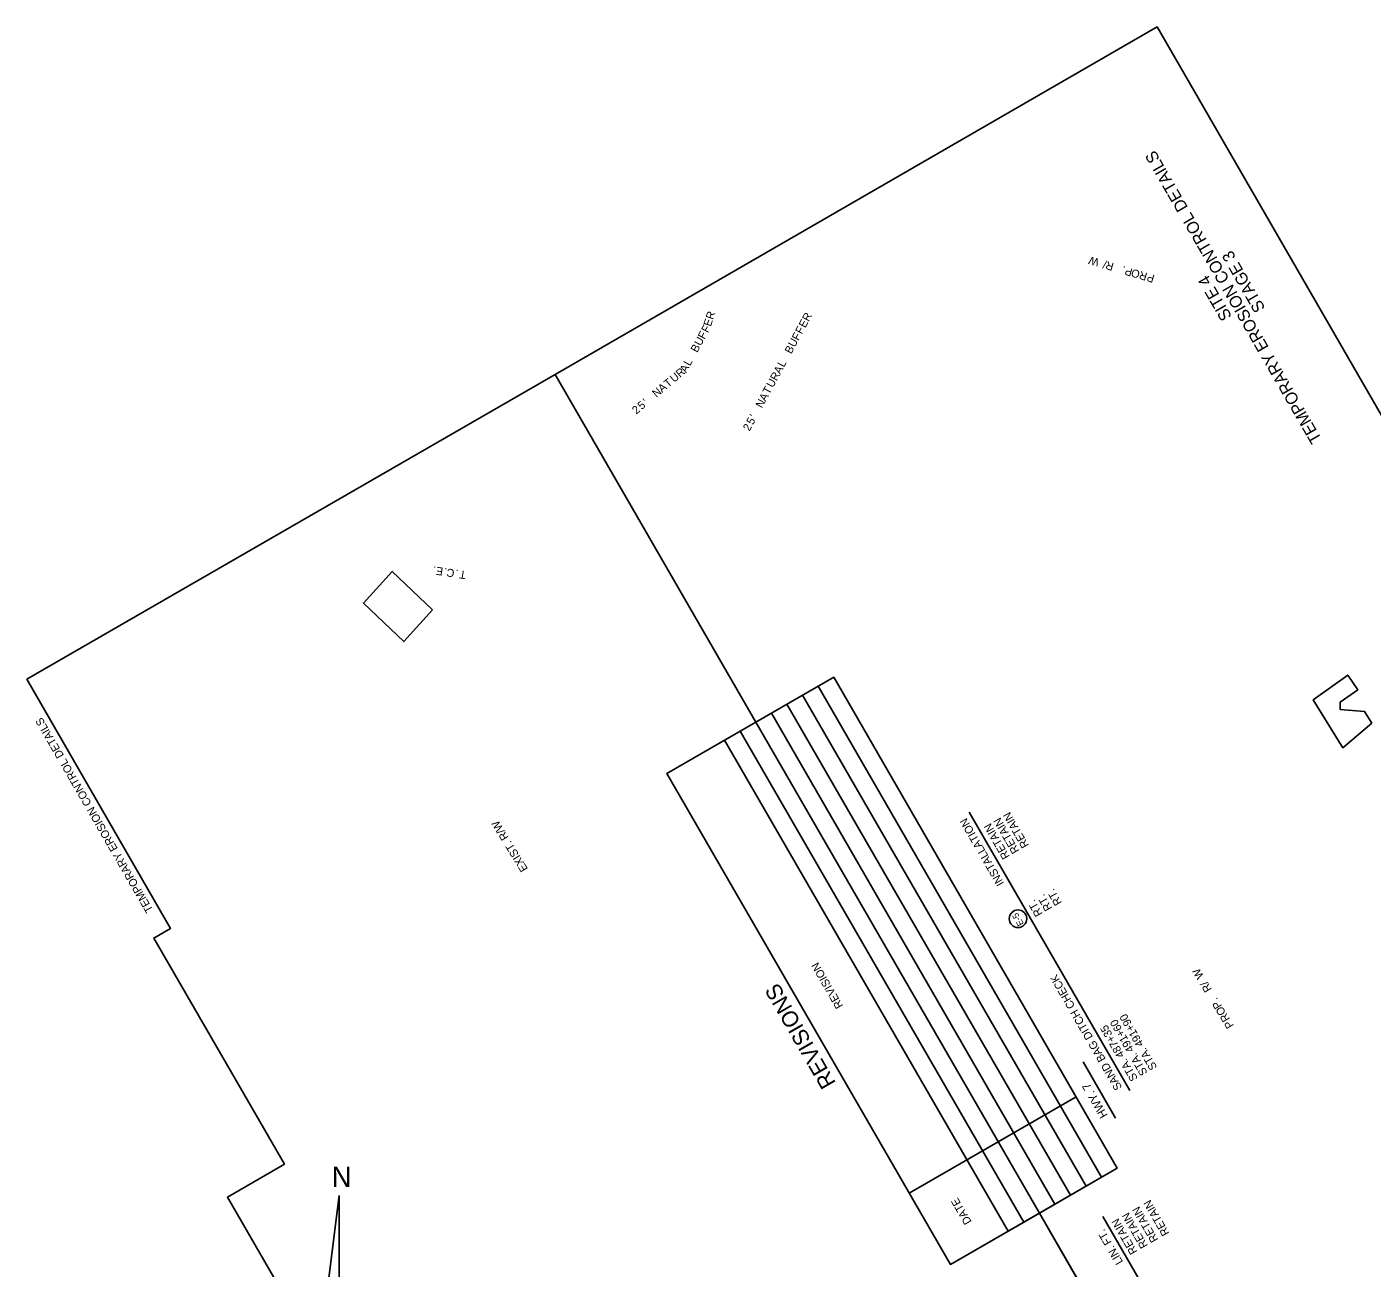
# Model space of a CAD drawing. Extents: x 956270 to 957915, y 1920520 to 1922423.
# Drawn here: x 956270 to 957279, y 1921493 to 1922423 of the extents above; entities that cross this region are included whole.
import ezdxf

# ---------------------------------------------------------------- set-up
doc = ezdxf.new("R2010")
doc.units = 0
for name, color, linetype in [('1', 7, 'Continuous'), ('44', 7, 'Continuous'), ('60', 7, 'Continuous'), ('63', 7, 'Continuous'), ('Default', 7, 'Continuous'), ('NO PLOT', 7, 'Continuous'), ('R_Draft', 7, 'Continuous')]:
    doc.layers.add(name, color=color, linetype=linetype)

msp = doc.modelspace()

# ---------------------------------------------------------------- linework, layer by layer
at = {"layer": '1'}
for p, q in [((956816.7, 1921902), (956666.2, 1922162.6)), ((957172.3, 1921286.1), (957029.2, 1921533.9))]:
    msp.add_line(p, q, dxfattribs=at)
msp.add_circle((957013.2, 1921754.6), 6.61, dxfattribs=at)
at = {"layer": '44'}
for p, q in [((957097.1, 1921625.8), (956976.5, 1921834.5)), ((957086.4, 1921605), (957062, 1921647.3)), ((957193.2, 1921329.7), (957076.8, 1921531.3))]:
    msp.add_line(p, q, dxfattribs=at)
at = {"layer": '63'}
for p, q in [((956504.3, 1921547), (956496.6, 1921485.5)), ((956504.3, 1921447), (956504.3, 1921547)), ((956504.3, 1921547), (956504.3, 1921470.1))]:
    msp.add_line(p, q, dxfattribs=at)
at = {"layer": 'Default'}
for p, q in [((956750, 1921863.5), (956875.1, 1921935.7)), ((957075.9, 1921560.9), (956863.4, 1921929)), ((957087.6, 1921567.7), (956875.1, 1921935.7)), ((957064.2, 1921554.2), (956851.7, 1921922.2)), ((957040.9, 1921540.7), (956828.4, 1921908.7)), ((957040.9, 1921540.7), (956828.4, 1921908.7)), ((957052.5, 1921547.4), (956840, 1921915.5)), ((957029.2, 1921533.9), (956816.7, 1921902)), ((957005.8, 1921520.4), (956793.3, 1921888.5)), ((957017.5, 1921527.2), (956805, 1921895.2)), ((956962.5, 1921495.4), (956750, 1921863.5)), ((956931.6, 1921548.9), (957056.7, 1921621.2)), ((956962.5, 1921495.4), (957087.6, 1921567.7))]:
    msp.add_line(p, q, dxfattribs=at)
at = {"layer": 'NO PLOT'}
for points in [[(957915.2, 1921041.6), (957117.5, 1922423.2), (956666.2, 1922162.6), (956816.7, 1921902), (956875.1, 1921935.7), (957087.6, 1921567.7), (957029.2, 1921533.9), (957172.3, 1921286.1), (957225.7, 1921317), (957397.1, 1921020.2), (957343.6, 1920989.3), (957463.8, 1920781)], [(957915.2, 1921041.6), (957117.5, 1922423.2), (956666.2, 1922162.6), (956816.7, 1921902), (956875.1, 1921935.7), (957087.6, 1921567.7), (957029.2, 1921533.9), (957172.3, 1921286.1), (957225.7, 1921317), (957397.1, 1921020.2), (957343.6, 1920989.3), (957463.8, 1920781)], [(957915.2, 1921041.6), (957117.5, 1922423.2), (956666.2, 1922162.6), (956816.7, 1921902), (956875.1, 1921935.7), (957087.6, 1921567.7), (957029.2, 1921533.9), (957172.3, 1921286.1), (957225.7, 1921317), (957397.1, 1921020.2), (957343.6, 1920989.3), (957463.8, 1920781)], [(957915.2, 1921041.6), (957117.5, 1922423.2), (956666.2, 1922162.6), (956816.7, 1921902), (956875.1, 1921935.7), (957087.6, 1921567.7), (957029.2, 1921533.9), (957172.3, 1921286.1), (957225.7, 1921317), (957397.1, 1921020.2), (957343.6, 1920989.3), (957463.8, 1920781)], [(957915.2, 1921041.6), (957117.5, 1922423.2), (956666.2, 1922162.6), (956816.7, 1921902), (956875.1, 1921935.7), (957087.6, 1921567.7), (957029.2, 1921533.9), (957172.3, 1921286.1), (957225.7, 1921317), (957397.1, 1921020.2), (957343.6, 1920989.3), (957463.8, 1920781)], [(957915.2, 1921041.6), (957117.5, 1922423.2), (956666.2, 1922162.6), (956816.7, 1921902), (956875.1, 1921935.7), (957087.6, 1921567.7), (957029.2, 1921533.9), (957172.3, 1921286.1), (957225.7, 1921317), (957397.1, 1921020.2), (957343.6, 1920989.3), (957463.8, 1920781)], [(957012.5, 1920520.4), (956420.5, 1921545.9), (956463.3, 1921570.6), (956365.4, 1921740.1), (956378, 1921747.4), (956270.3, 1921934.1), (956666.2, 1922162.6), (956816.7, 1921902), (956750, 1921863.5), (956962.5, 1921495.4), (957029.2, 1921533.9), (957172.3, 1921286.1), (957120.9, 1921256.4), (957292.2, 1920959.7), (957343.6, 1920989.3), (957463.8, 1920781)], [(957012.5, 1920520.4), (956420.5, 1921545.9), (956463.3, 1921570.6), (956365.4, 1921740.1), (956378, 1921747.4), (956270.3, 1921934.1), (956666.2, 1922162.6), (956816.7, 1921902), (956750, 1921863.5), (956962.5, 1921495.4), (957029.2, 1921533.9), (957172.3, 1921286.1), (957120.9, 1921256.4), (957292.2, 1920959.7), (957343.6, 1920989.3), (957463.8, 1920781)], [(957012.5, 1920520.4), (956420.5, 1921545.9), (956463.3, 1921570.6), (956365.4, 1921740.1), (956378, 1921747.4), (956270.3, 1921934.1), (956666.2, 1922162.6), (956816.7, 1921902), (956750, 1921863.5), (956962.5, 1921495.4), (957029.2, 1921533.9), (957172.3, 1921286.1), (957120.9, 1921256.4), (957292.2, 1920959.7), (957343.6, 1920989.3), (957463.8, 1920781)], [(957012.5, 1920520.4), (956420.5, 1921545.9), (956463.3, 1921570.6), (956365.4, 1921740.1), (956378, 1921747.4), (956270.3, 1921934.1), (956666.2, 1922162.6), (956816.7, 1921902), (956750, 1921863.5), (956962.5, 1921495.4), (957029.2, 1921533.9), (957172.3, 1921286.1), (957120.9, 1921256.4), (957292.2, 1920959.7), (957343.6, 1920989.3), (957463.8, 1920781)], [(957012.5, 1920520.4), (956420.5, 1921545.9), (956463.3, 1921570.6), (956365.4, 1921740.1), (956378, 1921747.4), (956270.3, 1921934.1), (956666.2, 1922162.6), (956816.7, 1921902), (956750, 1921863.5), (956962.5, 1921495.4), (957029.2, 1921533.9), (957172.3, 1921286.1), (957120.9, 1921256.4), (957292.2, 1920959.7), (957343.6, 1920989.3), (957463.8, 1920781)], [(957012.5, 1920520.4), (956420.5, 1921545.9), (956463.3, 1921570.6), (956365.4, 1921740.1), (956378, 1921747.4), (956270.3, 1921934.1), (956666.2, 1922162.6), (956816.7, 1921902), (956750, 1921863.5), (956962.5, 1921495.4), (957029.2, 1921533.9), (957172.3, 1921286.1), (957120.9, 1921256.4), (957292.2, 1920959.7), (957343.6, 1920989.3), (957463.8, 1920781)], [(956574.4, 1921986.1), (956552.8, 1921962.4), (956522.5, 1921991.3), (956544.1, 1922015)], [(957278.4, 1921901.1), (957273, 1921910), (957254.7, 1921911.4), (957254.7, 1921917), (957268, 1921926.3), (957260.4, 1921937.3), (957234.5, 1921918.7), (957256.8, 1921882.8)]]:
    msp.add_lwpolyline(points, close=True, dxfattribs=at)

# ---------------------------------------------------------------- texts
at = {"layer": '1'}
for s, height, p in [('TEMPORARY EROSION CONTROL DETAILS', 6, (956365.1, 1921761.2)), ('E-5 ', 4.8, (957017.7, 1921750.9))]:
    msp.add_text(s, height=height, rotation=120, dxfattribs=at).set_placement(p)
at = {"layer": '44'}
for s, height, p in [('INSTALLATION', 6, (957003, 1921781.2)), ('RETAIN', 6, (957014.4, 1921805.5)), ('RETAIN', 6, (957021.6, 1921809.7)), ('RETAIN', 6, (957007.2, 1921801.3)), ('RT.', 6, (957031.8, 1921758.3)), ('RT.', 6, (957039, 1921762.5)), ('RT.', 6, (957046.3, 1921766.6)), ('SAND BAG DITCH CHECK', 6, (957091.4, 1921628.1)), ('STA. 491+60', 6, (957110.5, 1921639.1)), ('STA. 491+90', 6, (957117.7, 1921643.2)), ('STA. 487+35', 6, (957103.2, 1921634.9)), ('HWY. 7', 6.25, (957080.7, 1921607.3)), ('RETAIN', 6, (957118.5, 1921514)), ('RETAIN', 6, (957126.9, 1921518.9)), ('RETAIN', 6, (957102.9, 1921505)), ('RETAIN', 6, (957110.7, 1921509.5)), ('LIN. FT.', 6, (957092.1, 1921497.3))]:
    msp.add_text(s, height=height, rotation=120, dxfattribs=at).set_placement(p)
at = {"layer": '60'}
for s, p in [('TEMPORARY EROSION CONTROL DETAILS', (957241.2, 1922114.1)), ('STAGE 3', (957198.8, 1922212.3)), ('SITE 4', (957173.8, 1922206.1))]:
    msp.add_text(s, height=9, rotation=120, dxfattribs=at).set_placement(p)
at = {"layer": '63'}
msp.add_text('N', height=15.4, rotation=360, dxfattribs=at).set_placement((956498.7, 1921553.4))
at = {"layer": 'Default'}
for s, height, p in [('REVISION', 6, (956882.3, 1921689.3)), ('REVISIONS', 12, (956877, 1921631.5)), ('DATE', 6, (956978.6, 1921527.4))]:
    msp.add_text(s, height=height, rotation=120, dxfattribs=at).set_placement(p)
at = {"layer": 'R_Draft'}
for s, rotation, p in [('W', 163.5297, (957074.5, 1922249.2)), ('/', 163.5297, (957080.1, 1922247.6)), ('R', 163.5297, (957085.5, 1922246)), ('.', 163.5297, (957094.1, 1922243.4)), ('P', 163.5297, (957099.5, 1922241.8)), ('O', 163.5297, (957105.1, 1922240.2)), ('R', 163.5297, (957110.6, 1922238.6)), ('P', 163.5297, (957116, 1922237)), ('E', 71.8782, (956782.9, 1922198.2)), ('R', 71.8782, (956784.6, 1922203.4)), ('E', 61.6353, (956853.7, 1922197.1)), ('R', 61.6353, (956856.3, 1922201.9)), ('U', 61.6353, (956775.4, 1922183.6)), ('F', 61.6353, (956778.1, 1922188.6)), ('F', 61.6353, (956780.7, 1922193.4)), ('F', 61.6353, (956848.6, 1922187.6)), ('F', 61.6353, (956851.1, 1922192.4)), ('B', 61.6353, (956772.7, 1922178.6)), ('B', 61.6353, (956843.2, 1922177.6)), ('U', 61.6353, (956845.8, 1922182.6)), ('L', 61.6353, (956767.3, 1922168.6)), ('L', 61.6353, (956837.7, 1922167.6)), ('U', 39.9648, (956755.4, 1922156.3)), ('R', 39.9648, (956759.8, 1922160)), ('A', 61.6353, (956764.5, 1922163.4)), ('R', 61.6353, (956832.3, 1922157.4)), ('A', 61.6353, (956835, 1922162.4)), ('N', 39.9648, (956742.1, 1922145.1)), ('A', 39.9648, (956746.4, 1922148.8)), ('T', 39.9648, (956750.9, 1922152.5)), ('T', 61.6353, (956826.7, 1922147.2)), ('U', 61.6353, (956829.5, 1922152.3)), ('5', 39.9648, (956731.1, 1922135.9)), ("'", 39.9648, (956735.2, 1922139.4)), ('N', 61.6353, (956821.3, 1922137)), ('A', 61.6353, (956824, 1922142)), ('2', 39.9648, (956727, 1922132.5)), ('5', 61.6353, (956814.5, 1922124.4)), ("'", 61.6353, (956817, 1922129.2)), ('2', 61.6353, (956811.9, 1922119.7)), ('.', 171.3895, (956577.2, 1922018.5)), ('E', 171.3895, (956582.6, 1922017.7)), ('.', 171.3895, (956585.5, 1922017.3)), ('C', 171.3895, (956591.1, 1922016.4)), ('.', 171.3895, (956594, 1922016)), ('T', 171.3895, (956599.8, 1922015.1)), ('EXIST. R/W', 121.4881, (956646, 1921792)), ('W', 121.1899, (957152.7, 1921711.6)), ('/', 121.1899, (957155.8, 1921706.6)), ('R', 121.1899, (957158.7, 1921701.7)), ('P', 121.1899, (957166.3, 1921689.2)), ('.', 121.1899, (957163.3, 1921694.1)), ('O', 121.1899, (957169.3, 1921684.2)), ('R', 121.1899, (957172.2, 1921679.4)), ('P', 121.1899, (957175.2, 1921674.5))]:
    msp.add_text(s, height=6, rotation=rotation, dxfattribs=at).set_placement(p)

doc.saveas('drawing.dxf')
